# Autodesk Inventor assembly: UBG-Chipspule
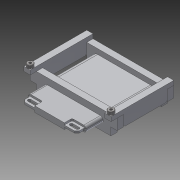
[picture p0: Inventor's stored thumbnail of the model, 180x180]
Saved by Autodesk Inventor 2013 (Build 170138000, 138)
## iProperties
Created: 2012-07
Part Number: UBG-Chipspule
Document SubType Name: Assembly
Designer: rYan
Mass: 71.9694 g
Surface Area: 158.531 cm^2
Volume: 16.4893 cm^3
Density: 4.36462 g/cm^3
Author: rYan
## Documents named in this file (5)
- D:\SVN\2013\Inventor\Kicker\Chip\UBG-Chipspule.iam
- D:\SVN\2013\Inventor\Kicker\Chip\Chip Spulenkoerper.ipt
- D:\SVN\2013\Inventor\Kicker\Chip\Chip Stoessel.ipt
- D:\SVN\2013\Inventor\Kicker\Straight\Straightfuehrung Hinten.ipt
- D:\SVN\2013\Inventor\Inhaltscenter\en-US\ISO 4762(2)\ISO 4762 - M2 x 4ISO.ipt
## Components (6 placed, 4 different names)
1. Chip Spulenkörper:1 — Mate:1, Passend:5, Fluchtend:2, Passend:6, Passend:13, Fluchtend:8, Passend:14, Mate:19
2. Chip Stoessel:1 — Mate:1, Mate:19
3. Straightführung:1 — Passend:5, Fluchtend:2, Passend:6, Mate:18
4. Straightführung:2 — Passend:13, Fluchtend:8, Passend:14, Mate:16
5. ISO 4762 M2 x 4:1 — Mate:16
6. ISO 4762 M2 x 4:2 — Mate:18
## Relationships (10: Mate 8, Flush 2)
- Mate:1: Chip Spulenkörper:1 ↔ Chip Stoessel:1
- Passend:5 [Mate]: Chip Spulenkörper:1 ↔ Straightführung:1
- Fluchtend:2 [Flush]: Chip Spulenkörper:1 ↔ Straightführung:1
- Passend:6 [Mate]: Chip Spulenkörper:1 ↔ Straightführung:1
- Passend:13 [Mate]: Chip Spulenkörper:1 ↔ Straightführung:2
- Fluchtend:8 [Flush]: Chip Spulenkörper:1 ↔ Straightführung:2
- Passend:14 [Mate]: Chip Spulenkörper:1 ↔ Straightführung:2
- Mate:16: Straightführung:2 ↔ ISO 4762 M2 x 4:1
- Mate:18: Straightführung:1 ↔ ISO 4762 M2 x 4:2
- Mate:19: Chip Spulenkörper:1 ↔ Chip Stoessel:1
